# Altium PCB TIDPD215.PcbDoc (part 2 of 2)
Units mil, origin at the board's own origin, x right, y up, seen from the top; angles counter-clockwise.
Board outline 3200 x 2750 mil, 6 copper layers (Top Layer, Layer 2 - GND, Layer 3 - Power, Layer 4 - VPOS B/C, VNEG B/D, Layer 5 - VPOS A/D, VNEG A/C, Bottom Layer), stack 97.668 mil thick; 154 components, 79 nets, 389 pads, 279 vias.
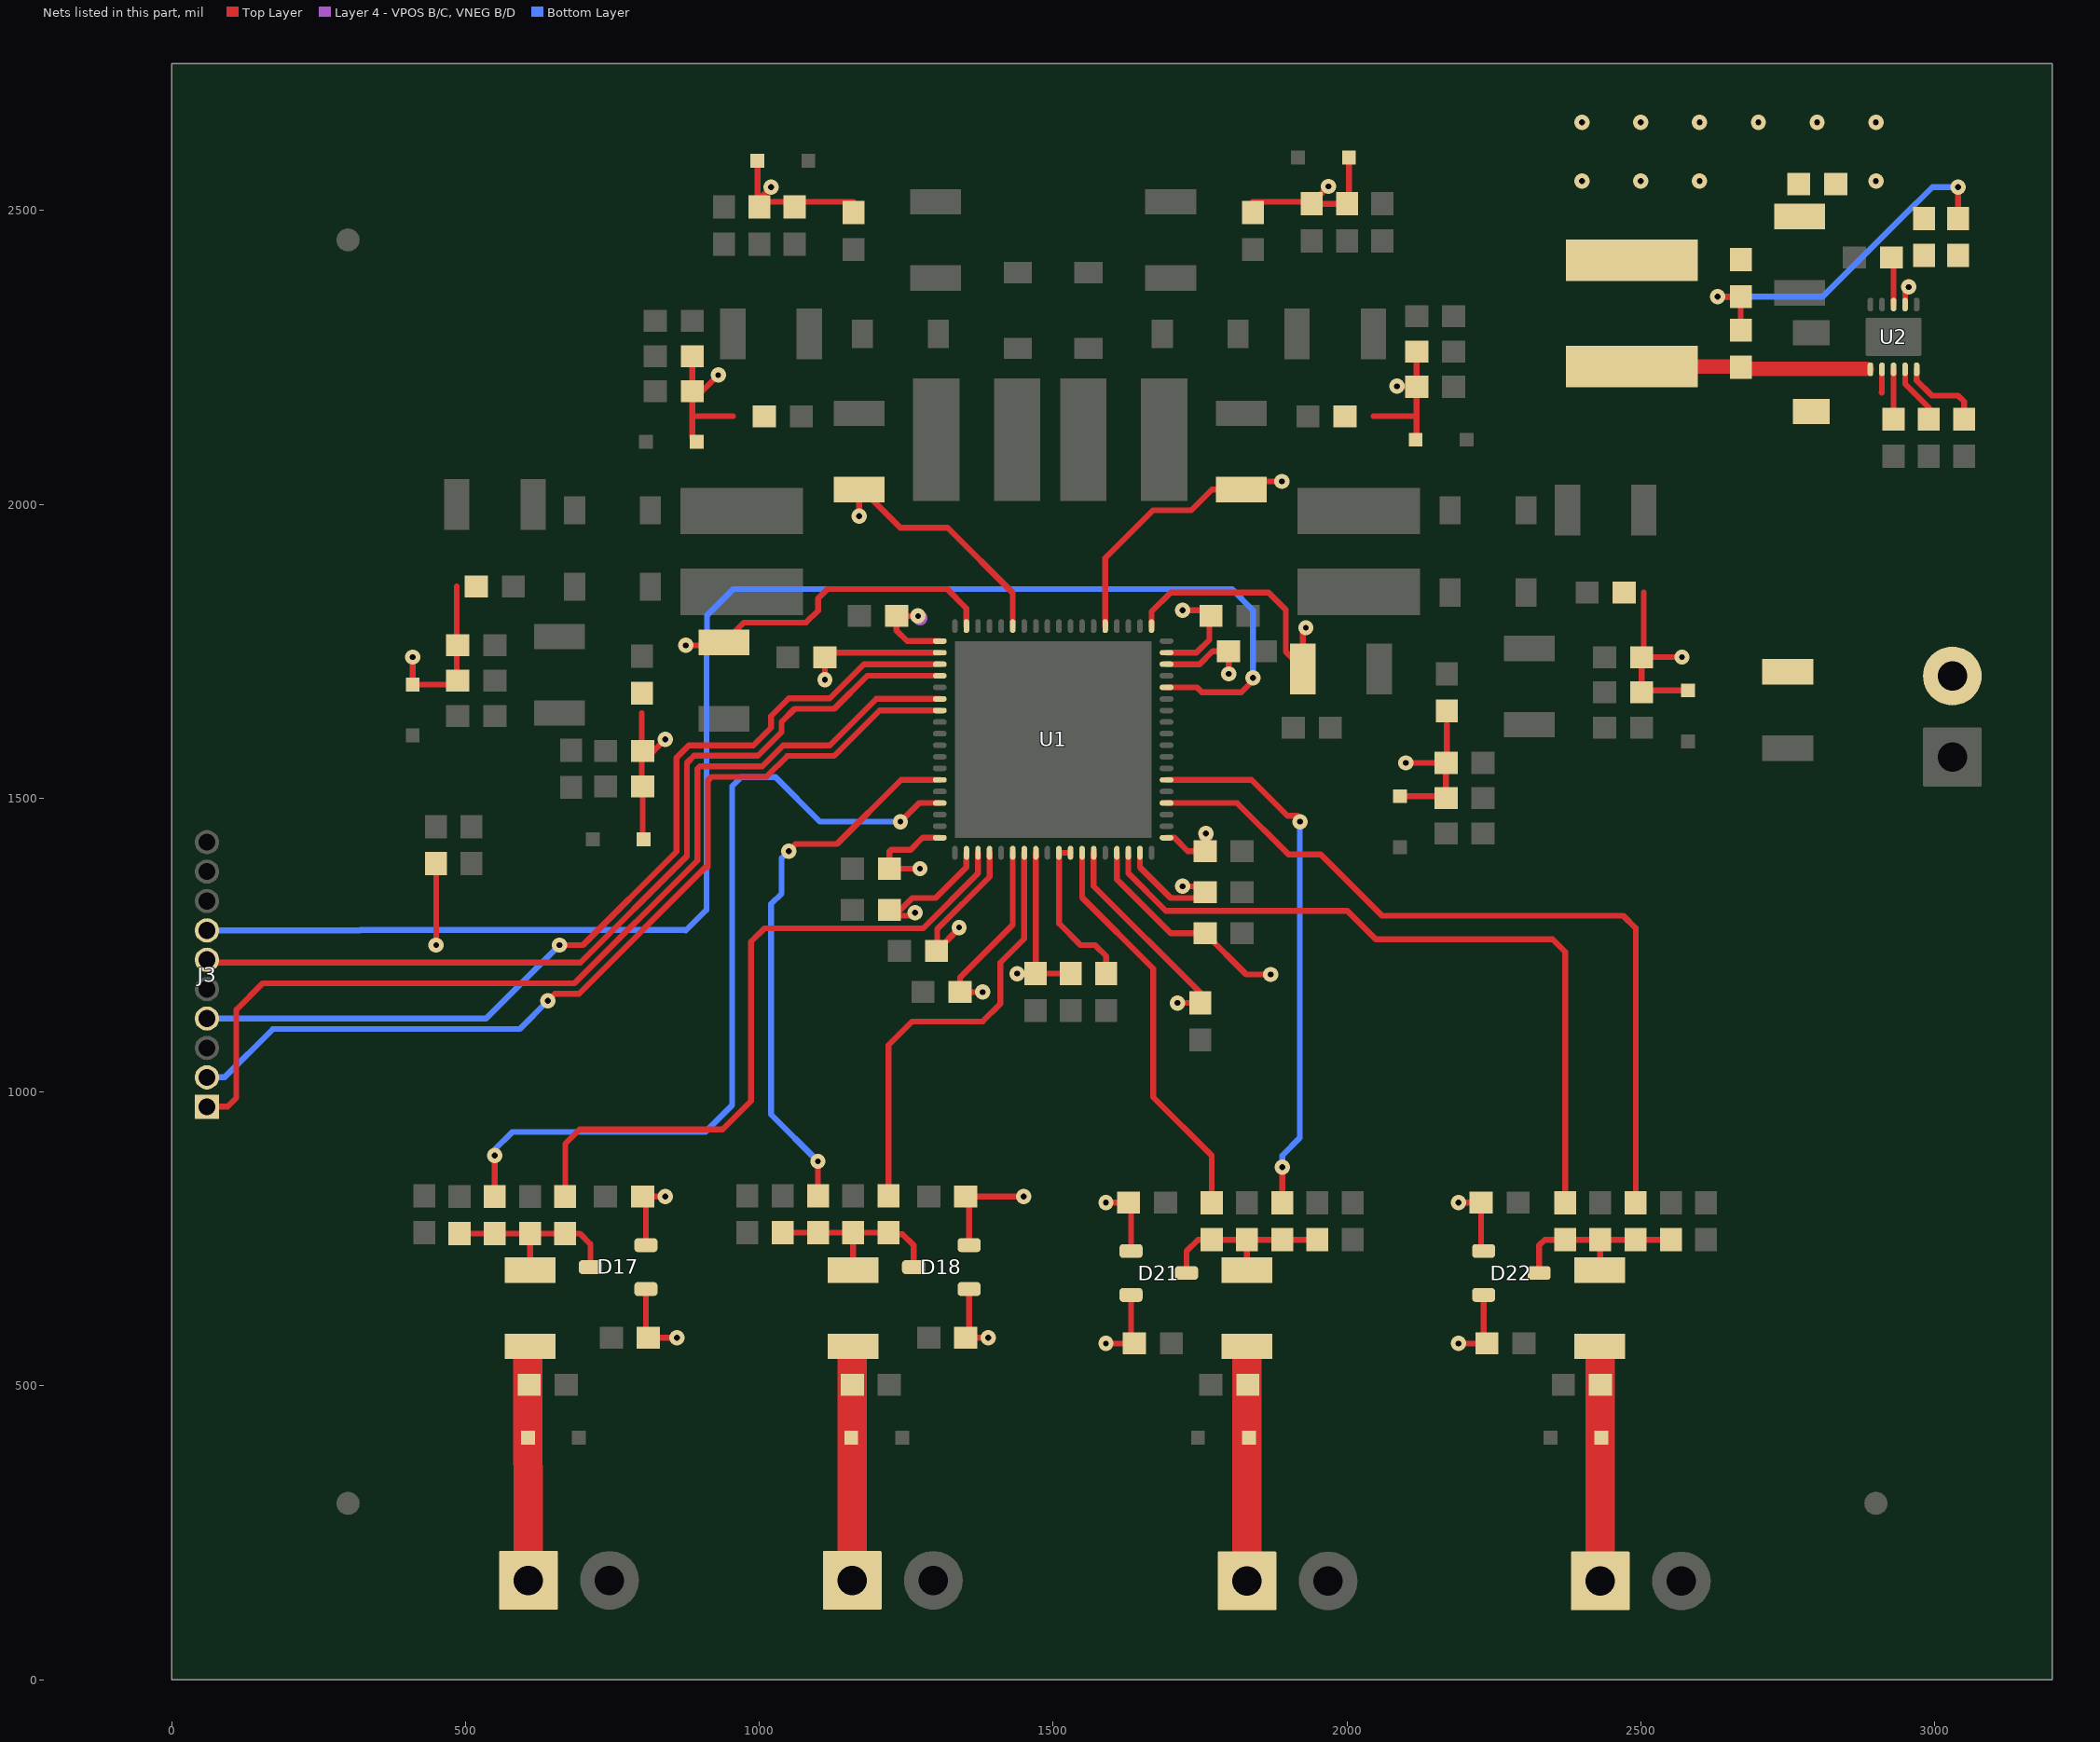
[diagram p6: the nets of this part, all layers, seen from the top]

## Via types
v1: diameter 26, hole 10, Top Layer to Bottom Layer, 226 vias
v2: diameter 19.68, hole 7.87, Top Layer to Bottom Layer, 53 vias

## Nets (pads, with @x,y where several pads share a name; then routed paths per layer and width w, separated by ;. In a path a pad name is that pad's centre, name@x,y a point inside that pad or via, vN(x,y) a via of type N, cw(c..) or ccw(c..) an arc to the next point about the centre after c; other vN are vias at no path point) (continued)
NetC44_1: C44.1 U1.46 U1.47 | length 272.8
  Top Layer w10: U1.47@1529.53,1407.09 U1.46@1509.84,1407.09 1510,1406.93 1510,1286.59 1546.59,1250 1571.02,1250 1590,1231.02 C44.1@1590,1201.5
NetC45_2: C45.2 C47.1 R9.2 | length 643
  Top Layer w10: v1(2630.5,2353.5) C45.2@2670,2353.5 R9.2@2670,2296.5 ; v1(3040,2540) 3040,2501.5 3052.5,2489 C47.1@3050,2486.5
  Bottom Layer w10: v1(2630.5,2353.5) 2809.5,2353.5 2945,2489 2996,2540 v1(3040,2540)
NetC47_2: C47.2 R11.1 R13.2 U2.8 | length 81.3
  Top Layer w10: R13.2@2926.5,2420 2930,2416.5 U2.8@2930,2340.12
NetC48_1: C48.1 U2.4 | length 101.7
  Top Layer w10: U2.4@2949.68,2229.88 2949.68,2205.32 2990,2165 C48.1@2990,2144.84
NetC49_1: C49.1 R12.1
NetC50_1: C50.1 D17.3 FB9.1 R17.2 R19.2 R21.2 | length 331.3
  Top Layer w10: C50.1@489.7,759.01 R21.2@609.7,759.01 ; FB9.1@609.7,696.96 R21.2@609.7,759.01 ; D17.3@712.46,702 712.46,741.01 694.46,759.01 R21.2@609.7,759.01
NetC51_1: C51.1 D18.3 FB10.1 R18.2 R20.2 R22.2 | length 332.3
  Top Layer w10: C51.1@1039.7,760.5 R22.2@1159.7,760.5 ; FB10.1@1159.7,696.96 R22.2@1159.7,760.5 ; D18.3@1262.46,702 1262.46,739.24 1243.7,758 1222.2,758 R20.2@1219.7,760.5 R22.2@1159.7,760.5
NetC56_1: C56.1 D19.2 FB9.2 J1.1 | length 392.1
  Top Layer w50: FB9.2@606,561.13 J1.1@607,169
NetC57_1: C57.1 D20.2 FB10.2 J2.1 | length 392.1
  Top Layer w50: J2.1@1158,169 FB10.2@1158,561.13
NetC60_1: C60.1 D21.3 FB11.1 R23.2 R25.2 R27.2 | length 319.6
  Top Layer w10: D21.3@1726.94,692 1726.94,729.24 1746.26,748.56 R27.2@1829.7,748.56 ; FB11.1@1829.7,696.96 R27.2@1829.7,748.56 ; C60.1@1949.7,748.56 R27.2@1829.7,748.56
NetC61_1: C61.1 D22.3 FB12.1 R24.2 R26.2 R28.2 | length 327.3
  Top Layer w10: D22.3@2326.94,692 2326.94,739.24 2336.26,748.56 R28.2@2431.02,748.56 ; FB12.1@2429.7,696.96 2431.02,698.28 R28.2@2431.02,748.56 ; C61.1@2551.02,748.56 R28.2@2431.02,748.56
NetC66_1: C66.1 D23.2 FB11.2 J4.1 | length 407.3
  Top Layer w10: D23.2@1829.7,415.31 1830,415.01 D23.2@1833.01,412 D23.2@1839.7,405.31
  Top Layer w50: FB11.2@1829.7,561.13 1830,415.01 J4.1@1830,168
NetC67_1: C67.1 D24.2 FB12.2 J5.1 | length 397.7
  Top Layer w50: J5.1@2431,166.03 FB12.2@2431,563.77
NetL5_1: L5.1 R9.1 U2.1 | length 404.8
  Top Layer w25: L5.1@2480,2234.45 R9.1@2669.06,2234.45 ; R9.1@2670,2233.5 2672.95,2230.55 2884.55,2230.55
NetR15_2: R15.2 U2.5 | length 144.6
  Top Layer w10: U2.5@2969.37,2229.88 2969.37,2210.91 2995.28,2185 3040,2185 3050,2175 R15.2@3050,2144.84
NetR16_2: R16.2 U2.3 | length 85
  Top Layer w10: R16.2@2930,2144.84 U2.3@2930,2229.88
PVDD/AVDD: C15.1 C16.1 C35.1 C36.1 C41.2 C42.2 C45.1 L5.2 R11.2 R12.2 U1.1 U1.5 U1.13 U1.17 U1.44 | length 2239.2
  Top Layer w10: v1(875,1760) 935.04,1760 C15.1@940,1764.96 973.9,1798.86 1079.66,1798.86 1100,1819.2 1100,1840 1115.87,1855.87 1319.4,1855.87 1352.36,1822.92 U1.17@1352.36,1792.91 ; v1(1170,1980) C16.1@1170,2025.04 1174.96,2025.04 1240,1960 1320.56,1960 1431.1,1849.45 U1.13@1431.1,1792.91 ; v1(1438.5,1201.5) C41.2@1470,1201.5 ; U1.44@1470.47,1407.09 1470.47,1201.97 C41.2@1470,1201.5 ; C42.2@1530,1201.5 C41.2@1470,1201.5 ; U1.5@1588.58,1792.91 1588.58,1908.58 1670,1990 1735,1990 1770,2025 C35.1@1820,2025.04 C35.1@1820,2025.04 1833.96,2039 v1(1889,2039) ; U1.1@1667.32,1792.91 1667.32,1817.32 1700,1850 1866.59,1850 1895.87,1820.72 1895.87,1749.17 C36.1@1925.04,1720 1925.04,1785.04 v1(1930,1790)
  other v1: 2400,2550 2500,2550 2600,2550 2900,2550 2400,2650 2500,2650 2600,2650 2700,2650 2800,2650 2900,2650
RESET: J3.7 R10.1 U1.68 | length 2771.3
  Top Layer w10: v1(450,1250) R10.1@450,1388.5 ; U1.68@1692.91,1688.58 1744.83,1688.58 1753.19,1680.22 1820.22,1680.22 1840,1700 v1(1840,1705)
  Bottom Layer w10: J3.7@60,1275 320,1275 320.87,1275.87 874.13,1275.87 875,1275 910,1310 910,1752.57 910.83,1753.41 910.83,1810.83 955.87,1855.87 1804.13,1855.87 1840,1820 v1(1840,1705) ; v1(450,1250) 450,1275
SPI_CS: J3.2 U1.25 | length 1592.1
  Top Layer w10: v1(640,1155) 652.13,1167.13 692.96,1167.13 908.27,1382.44 912.44,1382.44 912.44,1530 918.82,1536.38 1012.21,1536.38 1047.68,1571.85 1127.13,1571.85 1204.49,1649.21 U1.25@1307.09,1649.21
  Bottom Layer w10: J3.2@60,1025 90,1025 172.13,1107.13 592.13,1107.13 v1(640,1155)
SPI_MISO: J3.1 U1.24 | length 1713.8
  Top Layer w10: J3.1@60,975 95,975 110,990 110,1140 155,1185 685.56,1185 894.57,1394.01 894.57,1550 898.82,1554.25 1004.81,1554.25 1040.28,1589.72 1119.72,1589.72 1198.9,1668.9 U1.24@1307.09,1668.9
SPI_MOSI: J3.6 U1.22 | length 1554.5
  Top Layer w10: J3.6@60,1225 65,1220 695.28,1220 876.69,1401.42 876.69,1560 888.82,1572.13 997.4,1572.13 1037.87,1612.6 1037.87,1630 1060,1652.13 1127.4,1652.13 1183.55,1708.27 U1.22@1307.09,1708.27
SPI_SCLK: J3.4 U1.21 | length 1602.3
  Top Layer w10: v1(660,1250) 700,1250 858.82,1408.82 858.82,1568.82 880,1590 990,1590 1020,1620 1020,1640 1050,1670 1120,1670 1177.95,1727.95 U1.21@1307.09,1727.95
  Bottom Layer w10: J3.4@60,1125 535,1125 v1(660,1250)
VNEG_A: C6.1 C13.1 C18.1 C53.2 D6.2 D17.1 R2.1 R31.1 U1.19 U1.36 | length 707.7
  Top Layer w10: R2.1@800,1521.5 800,1645.04 ; R2.1@801.5,1520 801.5,1431.81 D6.2@803.31,1430 ; C6.1@801.5,1580 820,1580 v1(840,1600) ; D17.1@806.94,664.6 806.94,586.25 C53.2@811.2,582 v1(859.7,582) ; C18.1@1221.5,1380 v1(1273.37,1380) ; C18.1@1221.5,1390 1221.5,1409.62 1224,1412.13 1257.4,1412.13 1277.95,1432.68 U1.36@1307.09,1432.68 ; v1(1270,1810) C13.1@1233.45,1810 1233.45,1785.24 1251.36,1767.32 U1.19@1307.09,1767.32
  Layer 4 - VPOS B/C, VNEG B/D w25: v1(1270,1810) v1@1273.37,1806.63
VNEG_B: C8.1 C14.1 C20.1 C55.2 D8.2 D18.1 R4.1 R33.1 U1.20 U1.40 | length 897.7
  Top Layer w10: 885.95,2150 955.04,2150 ; R4.1@889.41,2248.82 R4.1@885.95,2252.29 C8.1@885.95,2192.29 ; D8.2@893.31,2106.69 885.95,2114.05 C8.1@885.95,2192.29 ; v1(930,2220) 902.29,2192.29 C8.1@885.95,2192.29 ; v1(1111.5,1701.5) C14.1@1111.5,1740 1119.13,1747.64 U1.20@1307.09,1747.64 ; C20.1@1301.5,1240 C20.1@1302.64,1241.14 ; v1(1340,1280) 1340,1278.5 C20.1@1302.64,1241.14 ; D18.1@1356.94,664.6 1356.94,587.75 C55.2@1351.2,582 v1(1389.7,582) ; U1.40@1391.73,1407.09 1391.73,1366.45 1302.64,1277.36 C20.1@1302.64,1241.14
VNEG_C: C26.1 C33.1 C38.1 C63.2 D14.2 D21.1 R6.1 R35.1 U1.51 U1.70 | length 905.8
  Top Layer w10: v1(1589.7,812) C63.2@1628.2,812 1632.46,807.75 D21.1@1632.46,729.4 ; U1.51@1608.27,1407.09 1608.27,1361.73 1700,1270 C38.1@1758.5,1270 1828.5,1200 v1(1870,1200) ; U1.70@1692.91,1727.95 1749.18,1727.95 1771.22,1750 C33.1@1798.5,1750 v1(1798.5,1711.5) ; 2044.96,2150 2118.5,2150 ; v1(2085,2201) 2117.5,2201 C26.1@2118.5,2200 ; D14.2@2118.5,2111.81 2118.5,2150 ; R6.1@2118.5,2260 C26.1@2118.5,2200 ; 2118.5,2150 C26.1@2118.5,2200
VNEG_D: C28.1 C34.1 C40.1 C65.2 D16.2 D22.1 R8.1 R37.1 U1.55 U1.71 | length 675.6
  Top Layer w10: U1.55@1692.91,1432.68 1706.3,1432.68 1728.98,1410 C40.1@1758.5,1410 ; U1.71@1692.91,1747.64 1743.58,1747.64 1765.94,1770 1765.94,1810 1755.94,1820 v1(1720,1820) ; C40.1@1760,1411.5 v1(1760,1440) ; D16.2@2090,1503.31 2165.2,1503.31 R8.1@2168.5,1506.61 ; v1(2100,1560) C28.1@2168.5,1560 ; R8.1@2168.5,1500 R8.1@2168.5,1506.61 ; 2170,1625.04 2170,1561.5 C28.1@2168.5,1560 ; v1(2189.7,812) C65.2@2228.2,812 2228.2,733.65 D22.1@2232.46,729.4 ; R8.1@2168.5,1506.61 C28.1@2168.5,1560
  Layer 4 - VPOS B/C, VNEG B/D w25: v1@1760,1437.2 v1(1760,1440)
VOUT_A: R19.1 U1.39 | length 1176.8
  Top Layer w10: R19.1@669.7,822 669.7,912 693.95,936.25 937.48,936.25 985.75,984.52 985.75,1255.75 1008.43,1278.43 1278.43,1278.43 1372.05,1372.05 U1.39@1372.05,1407.09
VOUT_B: R20.1 U1.43 | length 749.2
  Top Layer w10: R20.1@1220,823.8 1220,1080 1260,1120 1380,1120 1410,1150 1410,1220 1450.79,1260.79 U1.43@1450.79,1407.09
VOUT_C: R25.1 U1.48 | length 686.7
  Top Layer w10: U1.48@1549.21,1407.09 1549.21,1330.79 1670,1210 1670,992.3 ; 1669.7,992 1769.7,892 R25.1@1769.7,811.55
VOUT_D: R26.1 U1.52 | length 1260.5
  Top Layer w10: U1.52@1627.95,1407.09 1627.95,1372.05 1691.57,1308.43 2000.46,1308.43 2048.89,1260 2350,1260 2371.32,1238.68 R26.1@2371.32,811.85
VPOS_A: C5.2 C17.2 C52.2 D5.2 D17.2 R1.2 R30.1 U1.38 | length 635.9
  Top Layer w10: v1(410,1740) D5.2@410,1693.31 476.56,1693.31 485.04,1701.79 C5.2@485.04,1760 ; 485.04,1860 C5.2@485.04,1760 ; C5.2@486.83,1760 C5.2@485.04,1760 ; C52.2@801.2,822 v1(839.7,822) ; D17.2@806.94,739.4 C52.2@806.94,816.25 ; v1(1265,1305) 1260,1300 1231.5,1300 C17.2@1221.5,1310 1239.98,1310 1259.98,1330 1300,1330 1352.36,1382.36 U1.38@1352.36,1407.09
VPOS_B: C7.2 C19.2 C54.2 D7.2 D18.2 R3.2 R32.1 U1.42 | length 782.1
  Top Layer w10: D7.2@996.69,2584.45 996.69,2509.25 R3.2@1000,2505.94 ; v1(1020,2540) 1000,2520 R3.2@1000,2505.94 ; R32.1@1160,2514.96 1009.02,2514.96 R3.2@1000,2505.94 ; D18.2@1356.94,739.4 1356.94,816.25 C54.2@1351.2,822 v1(1449.7,822) ; v1(1380,1170) C19.2@1341.5,1170 1341.5,1194.76 1431.1,1284.37 U1.42@1431.1,1407.09
VPOS_C: C25.2 C37.2 C62.2 D13.2 D21.2 R5.2 R34.1 U1.49 | length 780.6
  Top Layer w10: U1.49@1568.9,1407.09 1568.9,1350.55 1750,1169.44 C37.2@1750,1151.5 v1(1711.5,1151.5) ; v1(1589.7,572) C62.2@1638.2,572 1632.46,577.75 D21.2@1632.46,654.6 ; R34.1@1840,2514.96 1936.54,2514.96 C25.2@1940,2511.5 ; v1(1968.54,2541.02) 1940,2512.48 C25.2@1940,2511.5 ; R5.2@2000,2511.5 C25.2@1940,2511.5 ; R5.2@2003.31,2514.8 D13.2@2003.31,2590
VPOS_D: C27.2 C39.2 C64.2 D15.2 D22.2 R7.2 R36.1 U1.53 | length 652.7
  Top Layer w10: U1.53@1647.64,1407.09 1647.64,1382.36 1700,1330 1748.5,1330 C39.2@1758.5,1340 1748.5,1350 v1(1720,1350) ; v1(2189.7,572) C64.2@2238.2,572 2232.46,577.75 D22.2@2232.46,654.6 ; R7.2@2501.5,1680 C27.2@2501.5,1740 ; R7.2@2504.8,1683.31 D15.2@2580,1683.31 ; 2504.96,1850 2504.96,1743.46 C27.2@2501.5,1740 ; v1(2570,1740) C27.2@2501.5,1740
VSENSEP_A: R17.1 U1.33 | length 1461.9
  Top Layer w10: R17.1@549.7,822 v1(549.7,892) ; v1(1240,1460) 1271.73,1491.73 U1.33@1307.09,1491.73
  Bottom Layer w10: v1(549.7,892) 549.7,902 579.7,932 907.95,932 953.83,977.87 953.83,1520.42 ; 954.13,1520.72 969.28,1535.87 1027.53,1535.87 1103.41,1460 v1(1240,1460)
VSENSEP_B: R18.1 U1.31 | length 939
  Top Layer w10: v1(1050,1410) 1062.13,1422.13 1132.13,1422.13 1241.1,1531.1 U1.31@1307.09,1531.1 ; R18.1@1099.7,823.5 v1(1099.7,882)
  Bottom Layer w10: 1019.7,1319.7 1019.7,962 v1(1099.7,882) ; 1020,1320 1037.87,1337.87 1037.87,1397.87 v1(1050,1410)
VSENSEP_C: R23.1 U1.60 | length 920.5
  Top Layer w10: U1.60@1692.91,1531.1 1837.79,1531.1 1898.89,1470 1915.75,1470 1915.75,1464.25 v1(1920,1460) ; R23.1@1889.7,811.55 v1(1889.7,872)
  Bottom Layer w10: v1(1889.7,872) 1889.7,892 1919.7,922 v1@1919.7,1459.7
VSENSEP_D: R24.1 U1.58 | length 1353.5
  Top Layer w10: U1.58@1692.91,1491.73 1812.99,1491.73 1900.6,1404.13 1955.32,1404.13 2059.44,1300 2470,1300 2491.32,1278.68 R24.1@2491.32,811.85
VSUP: C46.1 C68.1 J6.2 U2.2 U2.7 | length 72.9
  Top Layer w10: 2910,2190 2910.31,2190.31 U2.2@2910.31,2229.88 ; U2.7@2949.68,2340.12 2949.68,2364.68 2954.91,2369.91 v1(2955.87,2369.91)
pads on no net: FID1.1 FID2.1 FID3.1 J3.8 J3.10 U1.65 U2.6
copper on no net:
  other v1: 1500,2500

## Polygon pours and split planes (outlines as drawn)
VNEG_A on Layer 5 - VPOS A/D, VNEG A/C "VNEGA" (solid, remove dead copper, pour order 58): 1656,2749 201,2749 0,2950 0,0 1517,0 1519,-2 1520,-1 1520,189.3 1520,-16.16 1519,1170 1519,1415 1325,1415 1325.45,1415.45 1325.45,1491.46 1166.54,1491.46 1165,1493 1165.96,1492.04 1165.96,1483.75 1165.96,1453.68 1300,1319.64 1300,1229 954.79,1229 954.13,1228.33 954.13,844.13 807.24,697.4 806.84,697 368,697 368,1806 368,1815 374,1815 377,1815 710.86,1815 710.86,1484.64 712.05,1483.45 1101.59,1483.45 1101.59,1518.59 1103,1520 1104,1519 1313,1519 1313,1782.24 1313,1785 1310.24,1785 1659,1785
VPOS_A on Layer 5 - VPOS A/D, VNEG A/C "VPOSA" (solid, remove dead copper, pour order 62): 368,697 368,1558.97 368,1815 370.5,1817.5 709,1817.5 709,1486.5 710.86,1484.64 713.84,1481.67 1103.37,1481.67 1137.97,1481.67 1300,1319.64 1300,1229 954.79,1229 954.13,1228.33 954.13,860.68 954.13,844.28 807.24,697.4 806.84,697
VNEG_C on Layer 5 - VPOS A/D, VNEG A/C "VNEGC" (solid, remove dead copper, pour order 64): 1519,1415 1519,1 1520,0 3200,0 3200,2750 1656,2750 1656,1785 1657,1784 1658,1785 1687,1785 1687,1404.18 1690,1401.18 1691.18,1400 1979.96,1400 2406.54,1826.58 2699.29,1826.58 2699.29,437.55 2699.29,437.54 2120,437.54 2120,1258.19 1660,1258.19 1660,1415
VPOS_D on Layer 5 - VPOS A/D, VNEG A/C "VPOSD" (solid, remove dead copper, pour order 66): 2120,437.54 2699.29,437.54 2699.29,1826.58 2406.54,1826.58 2401.58,1826.58 1974,1399 1972,1397 1660,1397 1660,1260 2118,1260 2118,439.54 2120,437.54
VPOS_B on Layer 4 - VPOS B/C, VNEG B/D "VPOSB" (solid, remove dead copper, pour order 48): 1320,1782.85 1669.85,1782.85 1670,2750 0,2750 0,0 1526,0 1525.43,0.57 1525.43,546.58 1525.43,1225.57 1525,1226 1525.77,1226.77 1525.77,1242.52 1525.77,1411.23 1516,1421 1404,1421 1404,1270 1335,1201 1300,1166 1300,1080 1410,970 1410,430 854.25,430 854.45,2270.99 1320,2269.95
VNEG_B on Layer 4 - VPOS B/C, VNEG B/D "VNEGB" (solid, remove dead copper, pour order 50): 1320,1782.85 1320,2269.95 855.49,2269.95 854.45,2270.99 854.25,430 1410,430 1410,970 1300,1080 1300,1165 1300,1166 1402.97,1268.97 1404,1270 1404,1418 1320,1418
VPOS_C on Layer 4 - VPOS B/C, VNEG B/D "VPOSC" (solid, remove dead copper, pour order 54): 1525.77,1402.56 1525.77,1421 1720,1421 1720,1374 1724,1370 2070,1370 2070,720 2270,720 2270,1910 2268.51,1911.49 1669.87,1911.49 1669.87,2749.87 3200,2750 3200,0 3197,-3 1528,-3
VNEG_D on Layer 4 - VPOS B/C, VNEG B/D "VNEGD" (solid, remove dead copper, pour order 56): 2070,720 2270,720 2270,1910 1679,1910 1679,1409 1719.5,1409 1720,1408.5 1720,1370 2070,1370
VSUP on Layer 3 - Power "VSUP" (solid, remove dead copper, pour order 36): 2650,1650 2650,2516 2651,2517 3200,2517 3200,1651
PVDD/AVDD on Layer 3 - Power "PVDD/AVDD" (solid, remove dead copper, pour order 38): 0,0 3200,0 3200,1650 2650,1650 2650,2516 2651,2515 3200,2515 3200,2750 0,2750
GND on Top Layer "Top Layer GND" (solid, remove dead copper, pour order 40): -0.89,2754.49 -0.89,4.49 3189.11,4.49 3189.11,2754.49
GND on Layer 2 - GND "Layer 2 GND" (solid, remove dead copper, pour order 42): 0,0 3200,0 3200,2750 0,2750
GND on Bottom Layer "Bottom Layer GND" (solid, remove dead copper, pour order 44): 0,2750 0,0 3200,0 3200,2750

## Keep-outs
Keep-Out Layer:
  the board outline again, w10

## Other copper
Top Layer:
  region net NetC47_2: 2905,2395 3067.25,2395 3068.54,2396.3 3068.54,2445 2905,2445
  pour cut-out: 2365,2270 2365,2380 2609.02,2380 2609.02,2270
  region net VSUP: 2910,2205 2910,2195 2910,2185 2890,2185 2890,1908 3082,1908 3082,1650 2890,1650 2650,1650 2650,2195 2860,2195 2860,2205 2900,2205
  region net GND: 2894,2253 2881.86,2253 2710,2253 2710,2440 2894,2440 2894,2375 2916,2375 2916,2253
  region net NetC49_1: 2726,2468 2726,2575 2800,2575 2800,2513 2814,2513 2814,2468
  region net PVDD/AVDD: 2365,2380 2595,2380 2595,2395 2698.54,2395 2700,2396.46 2700,2590 2810,2590 2810,2526.3 2848.7,2526.3 2850,2525 2850,2455 2958.54,2455 3005,2455 3005,2501.46 3005,2670 2365,2670
  region net GND: 2911.3,2102 3068.7,2102 3068.7,2010.3 3069,2010 2911,2010
  region net NetC50_1: 471,779 470.7,778.7 470.7,675 749.7,675 749.7,779
  region net NetC51_1: 1021,780 1020,779 1020,675 1297,675 1298,676 1298,780
  region net NetC60_1: 1968,769 1968,675 1691,675 1691,769
  region net NetC61_1: 2569,768 2569,674 2288,674 2288,768
  region net VNEG_B: 866,2271 923,2271 923,2236 1018.88,2236 1020,2234.88 1020,2094.88 866.12,2094.88 866,2095
  region net NetC4_1: 1062,2107 1114.88,2107 1114.88,2239.88 1116,2241 1220,2241 1220,2349 1219,2349 1062,2349
  region net LP_B: 1340,1967 1340,2320 1339,2321 1249,2321 1249,2001 1310,2001
  region net NetC3_2: 1110,2360 1489,2360 1489,2361 1489,2450 1111,2450
  region net VPOS_B: 970,2480 1230,2480 1230,2550 1045,2550 1045,2610 970,2610
  region net LN_A: 1073,2040 781,2040 780,2039 780,1934 1153,1934 1166,1934 1169,1944
  region net NetC1_2: 740,2050 580,2050 580,2048 580,2046 580,1814 580,1810 590,1810 594,1810 650,1810 650,1920 740,1920
  region net VPOS_A: 520,1669 390,1669 390,1911 520,1911
  region net NetC2_1: 750,1890 660,1890 660,1800 616,1800 616,1730 850,1730 850,1810 750,1810
  region net VNEG_A: 740,1680 872,1680 872,1602 840,1570 840,1410 770,1410 770,1609 740,1609
  region net LN_B: 1399,2323 1478,2323 1478,1972 1444,1938 1444,1910 1399,1955
  region net LP_A: 790,1824 866,1824 866,1812 1073,1812 1081.1,1820.1 1081.1,1851.1 1103.75,1873.75 1086.5,1891 790,1891
  region net LN_C: 1511,2323 1512,2323 1590,2323 1590,2007 1574,1991 1524,1991 1511,2004
  region net NetC21_2: 1510,2360 1910,2360 1910,2450 1510,2450
  region net VPOS_C: 1790,2490 2031,2490 2031,2610 1960,2610 1960,2564.42 1960,2564.41 1959.59,2564 1790,2564
  region net LP_C: 1729,2005 1729,2323 1649,2323 1648,2322 1648,2005
  region net NetC22_1: 1760,2350 1940,2350 1941,2350 1941,2105 1891,2105 1891,2106 1891,2242 1763,2242 1761,2240
  region net VNEG_C: 1992,2098 2150,2098 2150,2278.7 2149.3,2278 2081,2278 2081,2220 2079,2218 1993,2218
  region net LN_D: 2249,2026 2251,2028 1914,2028 1846,1960 1846,1951 1862,1951 1863,1951 2249,1951
  region net LP_D: 2250,1890 1916,1890 1915,1889 1914,1890 1888,1890 1867,1869 1867,1868 1910,1825 1910,1812 2250,1812
  region net NetC24_1: 2264,1891 2265,1890 2265,1777 2119,1777 2118,1776 2118,1700 2359,1700 2362,1703 2362,1790 2331,1790 2330,1791 2330,1891
  region net NetC23_2: 2265,1947 2340,1947 2340,1800 2419,1800 2420,1801 2420,2044 2266,2044 2265,2045
  region net VPOS_D: 2470,1650 2620,1650 2620,1910 2470,1910
  region net VNEG_D: 2225.12,1657.11 2060.89,1657.11 2060.99,1470 2197,1470 2197,1588.54 2222.54,1588.54 2225,1591

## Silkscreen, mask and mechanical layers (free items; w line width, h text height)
M1 Board Outline:
  lines w10: 0,2750 0,0 3200,0 3200,2750 200,2750
M2 Board Dimensions:
  rectangle: 125,-400 500,-275
  rectangle: 0,-275 125,-150
  lines w7: 0,-275 1000,-275 ; 125,-400 125,-150 ; 250,-400 250,-150 ; 500,-400 500,-150 ; 750,-400 750,-150 ; 0,-400 0,-150 1000,-150 1000,-400 0,-400
M5 Assembly Top:
  lines w10: -292,-930.17 6308,-930.17 ; -292,-726.83 6310,-726.83 ; -292,-523.5 -292,-1133.5 3713,-1133.5 6310,-1133.5 6310,-523.5 -291.5,-523.5 -291.5,-1133.5 1284,-1133.5 ; 2173,-1133.5 2173,-523.5 ; 3440,-726.83 3440,-523.5 ; 4280,-726.83 4280,-523.5 ; 4902,-1140 4902,-937.17
  text "COMPONENTS MARKED 'DNP' SHOULD NOT BE POPULATED." at 1153.5,-318.5 h60
  text "ASSEMBLY VARIANT:" at 1153,-434 h60
  text ".VariantName" at 2189,-434 h60
  text "PCB VIEWED FROM TOP SIDE" at -228.5,-655.67 h60
  text "BOARD #:" at 2248,-655.67 h60
  text ".PRJ_Number" at 2793.5,-655.67 h60
  text "REV:" at 3638,-655.67 h60
  text ".PCB_Rev" at 3929.5,-655.67 h60
  text "SVN REV:" at 4476,-655.67 h60
  text ".VersionControl_RevNumber" at 4982,-655.67 h60
  text "TID #:" at 2248,-859 h60
  text ".TID" at 2793.5,-859 h60
  text "PLOT NAME =" at -228.5,-1064.34 h60
  text ".plot_File_Name" at 577,-1064.34 h60
  text "GENERATED    :" at 2250,-1064.34 h60
  text ".Print_Date" at 3119.5,-1064.34 h60
  text ".Print_Time" at 3848.5,-1064.34 h60
  text "TEXAS INSTRUMENTS" at 5113,-1064.34 h60
M6 Assembly Bottom:
  lines w10: -292.5,-727.33 6309.5,-727.33 ; -290.5,-930.67 6309.5,-930.67 ; 1115.5,-1140.5 1115.5,-937.67 ; 1737.5,-727.33 1737.5,-524 ; 2577.5,-727.33 2577.5,-524 ; 3844.5,-1134 3844.5,-524 ; 4733.5,-1134 6309,-1134 6309,-524 -292.5,-524 -292.5,-1134 2304.5,-1134 6309.5,-1134 6309.5,-524
  text "COMPONENTS MARKED 'DNP' SHOULD NOT BE POPULATED." at 6102,-318 h60
  text ".VariantName" at 5058,-434 h60
  text "ASSEMBLY VARIANT:" at 6097,-434 h60
  text ".VersionControl_RevNumber" at 1035.5,-656.17 h60
  text "SVN REV:" at 1541.5,-656.17 h60
  text ".PCB_Rev" at 2088,-656.17 h60
  text "REV:" at 2379.5,-656.17 h60
  text ".PRJ_Number" at 3224,-656.17 h60
  text "BOARD #:" at 3769.5,-656.17 h60
  text "PCB VIEWED FROM BOTTOM SIDE" at 6246,-656.17 h60
  text ".TID" at 3224,-859.5 h60
  text "TID #:" at 3769.5,-859.5 h60
  text "TEXAS INSTRUMENTS" at 904.5,-1064.84 h60
  text ".Print_Time" at 2169,-1064.84 h60
  text ".Print_Date" at 2898,-1064.84 h60
  text "GENERATED    :" at 3767.5,-1064.84 h60
  text ".plot_File_Name" at 5440.5,-1064.84 h60
  text "PLOT NAME =" at 6246,-1064.84 h60
M9 Title Sheet:
  drawing of 57 lines, arcs and shapes, not listed
  text "1" at 739.84,8036.5 h70
  text "2" at 3235.5,8036.5 h70
  text "3" at 5724.84,8036.5 h70
  text "4" at 8231.51,8036.5 h70
  text "5" at 10730.5,8036.5 h70
  text "6" at 13235.5,8036.5 h70
  text "A" at -416.5,6893.5 h70
  text "A" at 14383.5,6893.5 h70
  text "B" at -416.5,4513.5 h70
  text "B" at 14383.5,4513.5 h70
  text "C" at -416.5,2138.5 h70
  text "C" at 14383.5,2138.5 h70
  text "PROJECT TITLE:" at 11343.5,277.5 h45
  text ".PRJ_Title" at 11393.5,144.17 h70
  text "DESIGNED FOR:" at 11343.5,-23.5 h45
  text ".PRJ_Customer" at 11393.5,-163.5 h70
  text "D" at -416.5,-231.5 h70
  text "D" at 14383.5,-231.5 h70
  text "FILE NAME:" at 11343.5,-323.5 h45
  text ".PCB_File_Name_No_Path" at 11393.5,-443.5 h70
  text "Texas Instruments (TI) and/or its licensors do not warrant the accuracy or completeness of this specification" at 6374,-605.34 h45
  text "ENGINEER:" at 11343.5,-613.5 h45
  text "LAYOUT BY:" at 12848.5,-613.5 h45
  text "or any information contained therein. TI and/or its licensors do not warrant that this design will meet" at 6329.01,-718 h45
  text ".PRJ_Engineer" at 11393.5,-768.49 h70
  text ".PCB_Layout" at 12899,-768.49 h70
  text "the specifications, will be suitable for your application or fit for any particular purpose, or will operate in" at 6329.01,-830.67 h45
  text ".Layer_Name" at 577,-858.49 h60
  text "ALTIUM DESIGNER VERSION:" at 12848.5,-923.5 h45
  text "an implementation. TI and/or its licensors do not warrant that the design is production worthy. You should" at 6329.01,-943.33 h45
  text "completely validate and test your design implementation to confirm the system functionality for your application." at 6374,-1056 h45
  text ".print_Scale" at 11393.5,-1056.83 h70
  text ".Application_BuildNumber" at 12899,-1056.83 h70
  text "1" at 739.84,-1263.5 h70
  text "2" at 3235.5,-1263.5 h70
  text "3" at 5724.84,-1263.5 h70
  text "4" at 8231.51,-1263.5 h70
  text "5" at 10730.5,-1263.5 h70
  text "6" at 13235.5,-1263.5 h70
M10 Fab Notes:
  drawing of 185 lines, arcs and shapes, not listed
  text "DESIGN INFORMATION" at 12381.02,5910 h60
  text "MIN. TRACK WIDTH:" at 11736.46,5730 h60
  text "8" at 12832.7,5730 h60
  text "MIL" at 12987.46,5730 h60
  text "MIN. CLEARANCE:" at 11736.46,5598 h60
  text "0.2" at 12772.7,5598 h60
  text "mm" at 12987.46,5598 h60
  text "MIN. VIA PAD SIZE:" at 11736.46,5466 h60
  text "24" at 12802.71,5466 h60
  text "MIL" at 12987.46,5466 h60
  text "0.05mm (2MIL)" at 12431.46,5324.29 h60
  text "MINIMUM ANNULAR RING" at 11407.23,5320 h60
  text "EXTERNAL" at 13139.46,5320 h60
  text "PER" at 11607.23,5202 h60
  text "IPC-D-275 CLASS 2 LEVEL C" at 11827.23,5202 h60
  text "MIL, HOLES" at 13315.46,5089.71 h60
  text "+/-" at 12923,5089 h60
  text "+/-" at 13777,5089 h60
  text "REGISTRATION TOLERANCES:" at 11407.23,5084 h60
  text "METAL" at 12607,5084 h60
  text "5" at 13183.2,5084 h60
  text "3" at 14016.2,5084 h60
  text "MIL" at 14132.46,5084 h60
  text "MATERIAL:" at 11332.46,4874.54 h60
  text "FR-4 High Tg" at 12318.9,4734.21 h60
  text "FR-408" at 11753.46,4725.64 h60
  text "X" at 12165.46,4725.64 h60
  text "OTHER" at 13241.46,4725.64 h60
  text "62 MIL (1.6mm) +/-10%" at 12073.56,4562.92 h60
  text "THICKNESS:" at 11407.23,4558.64 h60
  text "X" at 11945.4,4558.64 h60
  text "OTHER" at 13358.46,4558.64 h60
  text "TOLERANCE:" at 11407.23,4400.64 h60
  text "X" at 12246.53,4400.64 h60
  text "ANSI IPC-6012 TYPE 3 CLASS 2" at 12433.48,4400.64 h60
  text "OTHER +/-" at 12433.46,4244.64 h60
  text "BOW & TWIST:" at 11407.23,4087.64 h60
  text "X" at 12246.53,4087.64 h60
  text "ANSI IPC-6012 TYPE 3 CLASS 2" at 12433.48,4087.64 h60
  text "OTHER +/-" at 12433.46,3929.13 h60
  text "DRILLING:" at 11332.46,3790.64 h60
  text "REFERENCE:" at 11407.23,3673.64 h60
  text "X" at 12055.46,3673.64 h60
  text "AS SHOWN" at 12242.46,3673.64 h60
  text "X" at 12956.46,3673.64 h60
  text "NC_DRILL FILES" at 13093.46,3673.64 h60
  text "PTH MIN COPPER THICKNESS:" at 11407.23,3515.64 h60
  text "X" at 12757.46,3515.64 h60
  text "1MIL" at 12894.46,3515.64 h60
  text "OTHER" at 13391.46,3515.64 h60
  text "BOARD FINISH:" at 11332.46,3356.64 h60
  text "SILKSCREEN:" at 11487.68,3238.64 h60
  text "X" at 12436.46,3238.64 h60
  text "TOP" at 12562.46,3238.64 h60
  text "X" at 12946.46,3238.64 h60
  text "BOTTOM" at 13073.46,3238.64 h60
  text "SILKSCREEN COLOR:" at 11487.68,3071.64 h60
  text "X" at 12435.42,3071.64 h60
  text "WHITE" at 12562.46,3071.64 h60
  text "OTHER" at 13073.46,3071.64 h60
  text "SOLDER RESIST COLOR:" at 11487.68,2901.64 h60
  text "X" at 12055.42,2742.44 h60
  text "GREEN" at 12182.46,2742.44 h60
  text "BLUE" at 12773.46,2742.44 h60
  text "OTHER" at 13311.46,2742.44 h60
  text "IMMERSION GOLD (ENIG)" at 12393.46,2553.92 h60
  text "ENEPIG" at 13731,2550.64 h60
  text "SURFACE FINISH:" at 11332.46,2549.64 h60
  text "X" at 12206.51,2549.64 h60
  text "IMM. TIN/SILVER OR EQUIV" at 11662,2392.64 h60
  text "OTHER" at 13093.46,2392.64 h60
  text "ARRAY/PANEL:" at 11332.46,2213.64 h60
  text "CUT AND TRIM PER MECH LAYER 1" at 12393.46,2209.35 h60
  text "N.C. ROUTE" at 12393.46,2057.64 h60
  text "X" at 13072.46,2057.64 h60
  text "V. SCORE" at 13259.46,2057.64 h60
  text "CERTIFICATION:" at 11332.46,1920.64 h60
  text "MATERIALS AND WORKMANSHIP FOR ALL PCBS" at 12057.46,1920.64 h60
  text "TO MEET OR EXCEED THE REQUIREMENTS OF:" at 12057.46,1822.64 h60
  text "X" at 11683.96,1686.13 h60
  text "ANSI IPC-A-600F CLASS ->" at 11822.96,1686.13 h60
  text "X" at 13462.02,1686.13 h60
  text "2" at 13580.96,1686.14 h60
  text "1" at 13265.96,1684.64 h60
  text "3" at 13934.96,1684.64 h60
  text "X" at 11686.02,1526.64 h60
  text "UL 94V-0" at 11822.96,1526.64 h60
  text "X" at 12498.02,1526.64 h60
  text "RoHS" at 12634.96,1526.64 h60
  text "OTHER" at 13279.36,1526.64 h60
  text "PER ORDER" at 13676.42,1526.64 h60
  text "ADDITIONAL REQUIREMENTS:" at 11332.46,1385.64 h60
  text "MICROSECTION:" at 11407.23,1270.64 h60
  text "YES" at 12312.96,1270.64 h60
  text "REQUIRED" at 13174.46,1114.49 h60
  text "BARE BOARD ELEC. TEST:" at 11407.23,1111.64 h60
  text "NONE" at 12712.96,1111.64 h60
  text "X" at 13047.46,1111.64 h60
  text "PER ORDER" at 13766.46,1111.64 h60
  text "MANUFACTURER'S UL:" at 11407.23,954.64 h60
  text "RAIL" at 12572.96,950.35 h60
  text "METAL" at 13064.77,950.35 h60
  text "X" at 13440,950 h60
  text "SILK" at 13576.46,950.35 h60
M11 Gerber Information:
  lines w10: -292,-930.17 6308,-930.17 ; -292,-726.83 6310,-726.83 ; -292,-523.5 -292,-1133.5 3713,-1133.5 6310,-1133.5 6310,-523.5 -291.5,-523.5 -291.5,-1133.5 1284,-1133.5 ; 2173,-1133.5 2173,-523.5 ; 3440,-726.83 3440,-523.5 ; 4280,-726.83 4280,-523.5 ; 4902,-1140 4902,-937.17
  text "ALL ARTWORK VIEWED FROM TOP SIDE" at -228.5,-655.67 h60
  text "BOARD #:" at 2248,-655.67 h60
  text ".PRJ_Number" at 2793.5,-655.67 h60
  text "REV:" at 3638,-655.67 h60
  text ".PCB_Rev" at 3929.5,-655.67 h60
  text "SVN REV:" at 4476,-655.67 h60
  text ".VersionControl_RevNumber" at 4982,-655.67 h60
  text "LAYER NAME =" at -228.5,-858.49 h60
  text "TID #:" at 2248,-859 h60
  text ".TID" at 2793.5,-859 h60
  text "PLOT NAME =" at -228.5,-1064.34 h60
  text ".plot_File_Name" at 577,-1064.34 h60
  text "GENERATED    :" at 2250,-1064.34 h60
  text ".Print_Date" at 3119.5,-1064.34 h60
  text ".Print_Time" at 3848.5,-1064.34 h60
  text "TEXAS INSTRUMENTS" at 5113,-1064.34 h60
M12 Stackup:
  drawing of 191 lines, arcs and shapes, not listed
  text "Layer" at 9790.58,7830 h60
  text "Name" at 10200.49,7830 h60
  text "Material" at 11130.23,7830 h60
  text "Thickness" at 11990,7830 h60
  text "Constant" at 12639.84,7830 h60
  text "Board Layer Stack" at 13209.7,7830 h60
  text "1" at 9790.58,7710 h60
  text "Top Overlay" at 10200.49,7710 h60
  text "2" at 9790.58,7590 h60
  text "Top Solder" at 10200.49,7590 h60
  text "Solder Resist" at 11130.23,7590 h60
  text "0.40mil" at 11990,7590 h60
  text "3.5" at 12639.84,7590 h60
  text "3" at 9790.58,7470 h60
  text "Top Layer" at 10200.49,7470 h60
  text "Copper" at 11130.23,7470 h60
  text "1.40mil" at 11990,7470 h60
  text "4" at 9790.58,7350 h60
  text "Dielectric1" at 10200.49,7350 h60
  text "FR-4" at 11130.23,7350 h60
  text "59.20mil" at 11990,7350 h60
  text "4.8" at 12639.84,7350 h60
  text "5" at 9790.58,7230 h60
  text "Bottom Layer" at 10200.49,7230 h60
  text "Copper" at 11130.23,7230 h60
  text "1.40mil" at 11990,7230 h60
  text "6" at 9790.58,7110 h60
  text "Bottom Solder" at 10200.49,7110 h60
  text "Solder Resist" at 11130.23,7110 h60
  text "0.40mil" at 11990,7110 h60
  text "3.5" at 12639.84,7110 h60
  text "7" at 9790.58,6990 h60
  text "Bottom Overlay" at 10200.49,6990 h60
Drill Drawing:
  lines w10: 5536.14,2865.04 5563.8,2878.87 5591.46,2865.04 5577.63,2892.7 5591.46,2920.36 5563.8,2906.53 5536.14,2920.36 5549.97,2892.7 5536.14,2865.04 ; 5536.14,3044.82 5591.46,3044.82 5563.8,2989.5 5536.14,3044.82 ; 5536.14,3113.96 5536.14,3127.79 5549.97,3141.62 5536.14,3155.45 5536.14,3169.28 5549.97,3169.28 5563.8,3155.45 5577.63,3169.28 5591.46,3169.28 5591.46,3155.45 5577.63,3141.62 5591.46,3127.79 5591.46,3113.96 5577.63,3113.96 5563.8,3127.79 5549.97,3113.96 5536.14,3113.96 ; 5536.14,3252.25 5549.97,3252.25 5563.8,3238.42 5577.63,3252.25 5591.46,3252.25 5577.63,3266.08 5591.46,3279.91 5577.63,3279.91 5563.8,3293.74 5549.97,3279.91 5536.14,3279.91 5549.97,3266.08 5536.14,3252.25
  lines w12: 5486,2827.71 7465.4,2827.71 ; 5486,3325.54 7465.4,3325.54 ; 5824.17,2703.25 5824.17,3450 ; 6156.28,2703.25 6156.28,3450 ; 6793.29,2703.25 6793.29,3450 ; 7052.64,2703.25 7052.64,3450 ; 5486,2703.25 7465.4,2703.25 7465.4,3450 5486,3450 5486,2703.25
  text "Symbol" at 5560.68,3362.88 h72
  text "Quantity" at 5861.51,3362.88 h72
  text "Finished Hole Size" at 6193.62,3362.88 h72
  text "Plated" at 6830.62,3362.88 h72
  text "Hole Type" at 7089.98,3362.88 h72
  text "53" at 5861.51,3238.42 h60
  text "7.87mil (0.200mm)" at 6193.62,3238.42 h60
  text "PTH" at 6830.62,3238.42 h60
  text "Round" at 7089.98,3238.42 h60
  text "226" at 5861.51,3113.96 h60
  text "10.00mil (0.254mm)" at 6193.62,3113.96 h60
  text "PTH" at 6830.62,3113.96 h60
  text "Round" at 7089.98,3113.96 h60
  text "10" at 5861.51,2989.5 h60
  text "28.74mil (0.730mm)" at 6193.62,2989.5 h60
  text "PTH" at 6830.62,2989.5 h60
  text "Round" at 7089.98,2989.5 h60
  text "10" at 5861.51,2865.04 h60
  text "50.00mil (1.270mm)" at 6193.62,2865.04 h60
  text "PTH" at 6830.62,2865.04 h60
  text "Round" at 7089.98,2865.04 h60
  text "299 Total" at 5861.51,2740.59 h60

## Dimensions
0,-400 to 1000,-400 on M2 Board Dimensions
0,0 to 3200,0 on M2 Board Dimensions
0,0 to 0,2750 on M2 Board Dimensions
